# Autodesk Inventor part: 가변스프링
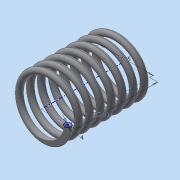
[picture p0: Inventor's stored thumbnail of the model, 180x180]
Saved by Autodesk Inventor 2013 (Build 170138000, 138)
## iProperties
Created: 2014-12
Part Number: 가변스프링
Material: 일반
Document SubType Name: Modeling
Designer: user
Density: 1 g/cm^3
Author: user
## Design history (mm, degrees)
sketch "스케치1"
  geometry: L1 (0, 0)-(17.5, 0); L2 (17.5, 0)-(17.5, 48.5); L3 (17.5, 48.5)-(0, 48.5); L4 (0, 48.5)-(0, 0); C1 r 2 at (17.5, 0)
  constraints: 8 end point, 2 parallel, 1 centre point, 1 coincident, 1 horizontal, 1 perpendicular
  dimensions: "d0" = 35 diameter of L2 L4; "d2" = 48.5 distance of L1.end L2.end (derived); "d4" = 4 diameter of C1
feature "코일1" sketch "스케치1" pitch "d5" = 10; turns "d7" = 7.5; dims "d6" = 48.5 (= d2), "d8" = 0, angle "d9" = 90 deg, angle "d10" = 90 deg, "d11" = 0, "d12" = 0
sketch "스케치2"
  geometry: L1 (-19.5, 0)-(-15.5, 0) reference; 1 further point
  constraints: 1 horizontal alignment
  node "절단 모서리 투영1"
node "작업 평면1"
sketch "스케치3"
  geometry: L1 (15.5, 0)-(19.5, 0) reference; 1 further point
  constraints: 1 horizontal alignment
extrude "돌출1" cut sketch "스케치3" distance "d13" = 10; taper "d14" = 0 deg
extrude "돌출2" cut sketch "스케치2" distance "d15" = 10; taper "d16" = 0 deg
node "솔리드1"
node "절단 모서리 투영2"
